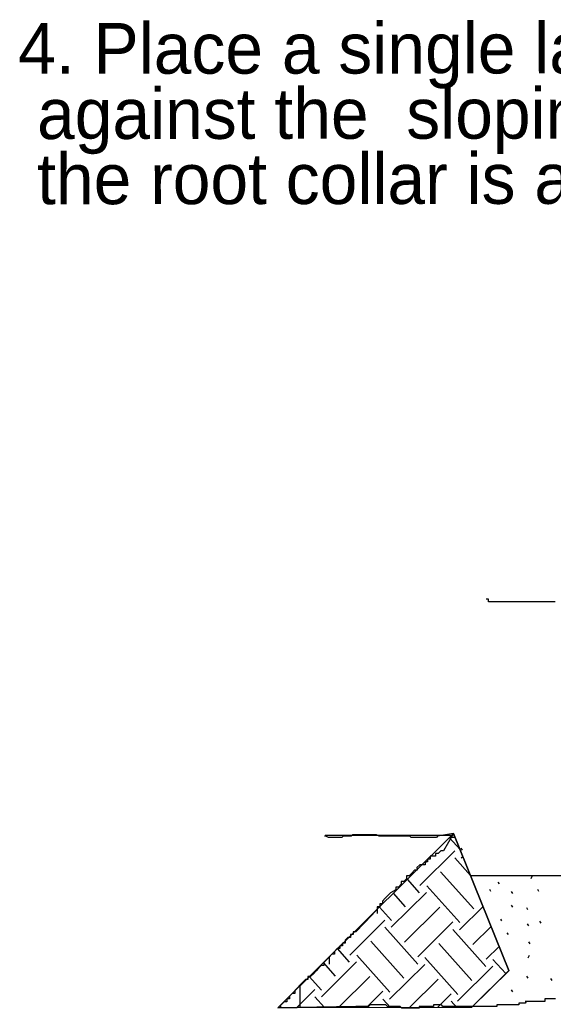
# Model space of a CAD drawing. Extents: x 816132 to 817815, y 885694 to 886789.
# Drawn here: x 816287.4 to 816358, y 886025.9 to 886156.5 of the extents above; entities that cross this region are included whole.
import ezdxf

# ---------------------------------------------------------------- set-up
doc = ezdxf.new("R2010")
doc.units = 0
doc.layers.add('Silt Fence Coir Fiber Wattle Break Detail CELL', color=7, linetype='Continuous')

msp = doc.modelspace()

# ---------------------------------------------------------------- linework, layer by layer
at = {"layer": 'Silt Fence Coir Fiber Wattle Break Detail CELL'}
for p, q in [((816321.51, 886025.96), (816344.77, 886048.97)), ((816344.5, 886048.73), (816327.79, 886048.71)), ((816344.52, 886048.73), (816327.81, 886048.71)), ((816344.29, 886048.49), (816344.97, 886048.49)), ((816344.77, 886048.97), (816352.09, 886030.87)), ((816352.09, 886030.87), (816344.77, 886048.97)), ((816345.63, 886046.86), (816344.22, 886048.42)), ((816340.3, 886042.1), (816344.95, 886046.7)), ((816345.73, 886047.05), (816345.89, 886046.8)), ((816345.79, 886045.76), (816345.99, 886045.96)), ((816341.07, 886045.31), (816341.07, 886045.09)), ((816347.01, 886043.44), (816344.92, 886045.75)), ((816347.45, 886039.04), (816343.06, 886043.91)), ((816347.02, 886043.41), (816364.73, 886043.43)), ((816348.77, 886043.42), (816364.74, 886043.43)), ((816355.03, 886043.05), (816355.19, 886043.42)), ((816340.28, 886041.15), (816338.67, 886042.93)), ((816345.59, 886037.2), (816341.21, 886042.07)), ((816350.62, 886042.56), (816350.78, 886042.31)), ((816336.53, 886036.59), (816341.18, 886041.19)), ((816338.42, 886039.31), (816336.81, 886041.1)), ((816349.51, 886041.61), (816349.67, 886041.36)), ((816352.4, 886041.3), (816352.55, 886041.06)), ((816355.85, 886041.61), (816356.01, 886041.36)), ((816345.57, 886036.25), (816348.67, 886039.32)), ((816352.4, 886039.49), (816352.55, 886039.24)), ((816334.64, 886038.95), (816334.64, 886038.42)), ((816336.56, 886037.47), (816334.95, 886039.25)), ((816338.29, 886034.64), (816342.94, 886039.24)), ((816354.41, 886039.19), (816354.57, 886038.94)), ((816331.04, 886032.92), (816335.69, 886037.53)), ((816340.05, 886032.69), (816344.69, 886037.29)), ((816350.96, 886037.68), (816351.12, 886037.43)), ((816354.51, 886037.02), (816354.67, 886036.77)), ((816356.14, 886037.38), (816356.3, 886037.13)), ((816340.05, 886031.71), (816335.66, 886036.58)), ((816349.05, 886031.4), (816344.67, 886036.28)), ((816347.33, 886034.3), (816349.74, 886036.69)), ((816351.82, 886035.86), (816351.98, 886035.61)), ((816338.19, 886029.86), (816333.81, 886034.74)), ((816347.2, 886029.56), (816342.81, 886034.44)), ((816354.7, 886034.65), (816354.86, 886034.41)), ((816331.02, 886031.97), (816329.4, 886033.77)), ((816336.34, 886028.02), (816331.95, 886032.9)), ((816349.08, 886032.35), (816350.8, 886034.06)), ((816354.64, 886032.55), (816354.8, 886032.92)), ((816327.28, 886027.41), (816331.92, 886032.02)), ((816329.16, 886030.13), (816327.54, 886031.93)), ((816328.3, 886032.68), (816328.3, 886031.71)), ((816336.31, 886027.07), (816340.96, 886031.68)), ((816345.34, 886027.72), (816340.95, 886032.59)), ((816351.67, 886030.46), (816349.98, 886032.33)), ((816345.31, 886026.84), (816349.96, 886031.45)), ((816352.09, 886030.87), (816347.12, 886025.98)), ((816352.11, 886030.87), (816347.14, 886025.98)), ((816327.3, 886028.29), (816325.68, 886030.09)), ((816329.54, 886025.97), (816333.68, 886030.07)), ((816338.93, 886025.98), (816342.71, 886029.73)), ((816354.42, 886030.12), (816354.58, 886029.87)), ((816357.59, 886029.82), (816357.75, 886029.57)), ((816324.02, 886025.97), (816326.43, 886028.35)), ((816324.42, 886028.85), (816324.42, 886025.97)), ((816333.27, 886025.97), (816335.43, 886028.12)), ((816342.65, 886025.98), (816344.47, 886027.78)), ((816352.41, 886028.3), (816352.56, 886028.05)), ((816321.87, 886026.32), (816321.87, 886025.96)), ((816327.7, 886025.97), (816326.4, 886027.4)), ((816336.42, 886025.97), (816335.41, 886027.1)), ((816345.21, 886025.98), (816344.44, 886026.83)), ((816347.12, 886025.98), (816321.51, 886025.96))]:
    msp.add_line(p, q, dxfattribs=at)
for points in [[(816358.22, 886079.6), (816357.86, 886079.6), (816357.51, 886079.6), (816357.16, 886079.6), (816356.81, 886079.6), (816356.45, 886079.6), (816356.1, 886079.6), (816355.75, 886079.6), (816355.4, 886079.6), (816355.05, 886079.6), (816354.69, 886079.6), (816354.34, 886079.6), (816353.99, 886079.6), (816353.64, 886079.6), (816353.29, 886079.6), (816352.93, 886079.6), (816352.58, 886079.6), (816352.23, 886079.6), (816351.88, 886079.6), (816351.53, 886079.6), (816351.17, 886079.6), (816350.82, 886079.6), (816350.47, 886079.6), (816350.12, 886079.59), (816349.77, 886079.59), (816349.41, 886079.59), (816349.41, 886079.96), (816349.06, 886079.96), (816349.06, 886079.96)], [(816344.77, 886048.97), (816343.45, 886046.71), (816343.1, 886046.71), (816342.75, 886046.34), (816342.4, 886046.34), (816342.4, 886045.97), (816342.05, 886045.97), (816341.69, 886045.97), (816341.69, 886045.6), (816341.34, 886045.6), (816341.34, 886045.23), (816340.99, 886045.23), (816340.99, 886044.86), (816340.64, 886044.86), (816340.29, 886044.86), (816339.93, 886044.49), (816339.94, 886044.12), (816339.58, 886044.12), (816339.23, 886043.75), (816338.88, 886043.38), (816338.53, 886043.38), (816338.53, 886043.01), (816338.18, 886042.64), (816337.82, 886042.64), (816337.82, 886042.27), (816337.47, 886041.9), (816337.12, 886041.9), (816337.12, 886041.53), (816336.42, 886041.16), (816336.07, 886040.79), (816335.71, 886040.42), (816335.36, 886040.05), (816335.36, 886039.68), (816335.01, 886039.68), (816335.01, 886039.31), (816334.66, 886039.31), (816334.66, 886038.94), (816334.31, 886038.57), (816333.95, 886038.2), (816333.6, 886037.83), (816333.25, 886037.46), (816332.9, 886037.09), (816332.55, 886036.72), (816332.2, 886036.35), (816331.84, 886035.98), (816331.49, 886035.98), (816331.49, 886035.61), (816331.14, 886035.61), (816331.14, 886035.24), (816330.79, 886035.24), (816330.44, 886034.87), (816330.44, 886034.5), (816330.08, 886034.5), (816330.09, 886034.13), (816329.73, 886034.13), (816329.73, 886033.76), (816329.38, 886033.76), (816329.03, 886033.39), (816329.03, 886033.02), (816328.68, 886033.02), (816328.33, 886032.65), (816327.97, 886032.28), (816327.62, 886031.91), (816327.62, 886031.55), (816327.27, 886031.54), (816326.92, 886031.18), (816326.57, 886030.81), (816326.22, 886030.43), (816325.86, 886030.07), (816325.51, 886030.07), (816325.51, 886029.7), (816325.16, 886029.7), (816324.81, 886029.33), (816324.46, 886028.96), (816324.11, 886028.59), (816323.75, 886028.22), (816323.75, 886027.85), (816323.4, 886027.85), (816323.05, 886027.48), (816323.05, 886027.11), (816322.7, 886027.11), (816322.7, 886026.74), (816322.35, 886026.74), (816321.51, 886025.96), (816321.51, 886025.96)], [(816344.77, 886048.97), (816342.66, 886048.65), (816342.49, 886048.46), (816342.13, 886048.46), (816341.78, 886048.46), (816341.43, 886048.46), (816341.08, 886048.46), (816340.73, 886048.46), (816340.37, 886048.46), (816340.02, 886048.46), (816339.67, 886048.46), (816339.14, 886048.46), (816338.97, 886048.64), (816338.61, 886048.64), (816338.09, 886048.64), (816337.73, 886048.64), (816337.2, 886048.64), (816336.85, 886048.64), (816336.32, 886048.64), (816335.8, 886048.64), (816335.44, 886048.64), (816334.92, 886048.64), (816334.56, 886048.82), (816334.21, 886048.82), (816333.86, 886048.82), (816333.51, 886048.82), (816333.16, 886048.82), (816332.8, 886048.82), (816332.45, 886048.82), (816332.1, 886048.82), (816331.75, 886048.82), (816331.4, 886048.82), (816331.22, 886048.64), (816330.87, 886048.64), (816330.52, 886048.64), (816330.16, 886048.64), (816329.99, 886048.45), (816329.64, 886048.45), (816329.28, 886048.45), (816328.93, 886048.45), (816328.58, 886048.45), (816328.23, 886048.45), (816327.88, 886048.63), (816327.7, 886048.63)], [(816334.36, 886026.32), (816334.15, 886026.32), (816333.94, 886026.32), (816333.73, 886026.32), (816333.52, 886026.1), (816333.31, 886026.1), (816333.1, 886026.1), (816332.89, 886026.1), (816332.68, 886026.1), (816332.47, 886026.1), (816332.26, 886026.1), (816332.05, 886026.1), (816331.84, 886026.1), (816321.51, 886025.96), (816321.51, 886025.96), (816331.84, 886026.1)], [(816354.38, 886026.76), (816354.26, 886026.56), (816354.05, 886026.56), (816353.84, 886026.56), (816353.63, 886026.56), (816353.42, 886026.56), (816353.42, 886026.34), (816353.21, 886026.34), (816353, 886026.34), (816352.79, 886026.34), (816352.58, 886026.34), (816352.37, 886026.34), (816352.16, 886026.34), (816351.95, 886026.34), (816351.74, 886026.34), (816351.53, 886026.34), (816351.33, 886026.34), (816351.12, 886026.34), (816350.91, 886026.34), (816350.7, 886026.33), (816350.49, 886026.34), (816350.49, 886026.11), (816350.28, 886026.11), (816350.07, 886026.11), (816349.86, 886026.11), (816349.65, 886026.11), (816349.44, 886026.11), (816349.23, 886026.11), (816349.02, 886026.11), (816348.81, 886026.11), (816348.6, 886026.11), (816348.39, 886026.11), (816348.18, 886026.11), (816347.97, 886026.11), (816347.76, 886026.11), (816347.55, 886026.11), (816347.35, 886026.11), (816347.13, 886026.11), (816346.93, 886026.11), (816346.72, 886026.11), (816346.51, 886026.11), (816346.3, 886026.11), (816346.09, 886026.11), (816345.88, 886026.11), (816345.67, 886026.11), (816345.46, 886026.11), (816345.25, 886026.11), (816345.04, 886026.11), (816344.83, 886026.11), (816344.62, 886026.11), (816344.41, 886026.11), (816344.2, 886026.11), (816343.99, 886026.11), (816343.78, 886026.11), (816343.57, 886026.11), (816343.36, 886026.11), (816343.16, 886026.33), (816342.95, 886026.33), (816342.74, 886026.33), (816342.53, 886026.33), (816342.32, 886026.33), (816342.11, 886026.33), (816342.11, 886026.11), (816341.9, 886026.11), (816341.69, 886026.11), (816341.48, 886026.11), (816341.27, 886026.11), (816341.06, 886026.11), (816340.85, 886026.11), (816340.64, 886026.11), (816340.43, 886026.11), (816340.22, 886026.11), (816340.22, 886025.89), (816340.01, 886025.89), (816339.8, 886025.89), (816339.59, 886025.89), (816339.39, 886025.89), (816339.18, 886025.89), (816338.97, 886025.89), (816338.76, 886025.89), (816338.55, 886025.89), (816338.34, 886025.89), (816338.13, 886025.89), (816337.92, 886025.89), (816337.71, 886026.1), (816337.5, 886026.1), (816337.29, 886026.1), (816337.08, 886026.1), (816336.87, 886026.1), (816336.66, 886026.1), (816336.45, 886026.1), (816336.24, 886026.1), (816336.03, 886026.1), (816335.82, 886026.32), (816335.61, 886026.32), (816335.4, 886026.32), (816335.19, 886026.32), (816334.99, 886026.32), (816334.78, 886026.32), (816334.57, 886026.32), (816334.36, 886026.32)], [(816358.25, 886027.13), (816357.9, 886027.13), (816357.55, 886027.13), (816357.2, 886027.13), (816356.84, 886027.13), (816356.84, 886026.76), (816356.14, 886026.76), (816355.44, 886026.76), (816355.08, 886026.76), (816354.73, 886026.76), (816354.38, 886026.76), (816354.26, 886026.76)]]:
    msp.add_lwpolyline(points, dxfattribs=at)

# ---------------------------------------------------------------- texts
for s, p in [('4. Place a single layer of plants ', (816287.17, 886149.4)), (' against the  sloping end so that ', (816287.18, 886140.78)), (' the root collar is at ground level.', (816287.19, 886132.16))]:
    msp.add_text(s, height=6.7041, rotation=0.045, dxfattribs=at).set_placement(p)

doc.saveas('drawing.dxf')
